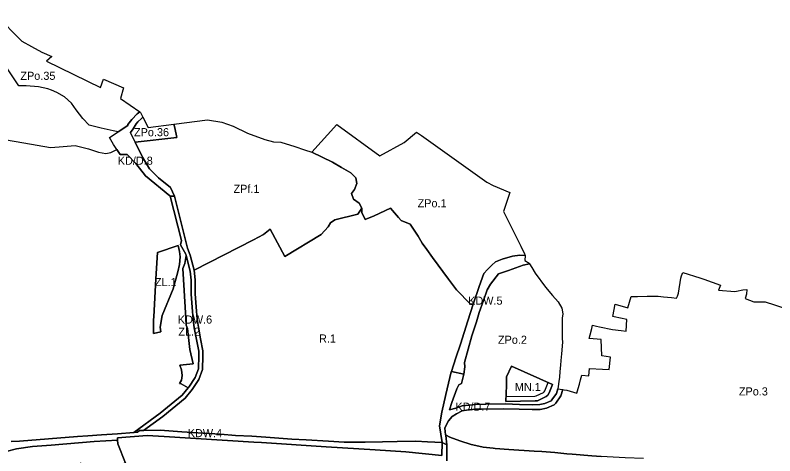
# Model space of a CAD drawing. Extents: x 7418114 to 7422197, y 5546299 to 5548348.
# Drawn here: x 7420780 to 7421715, y 5546924 to 5547467 of the extents above; entities that cross this region are included whole.
import ezdxf

# ---------------------------------------------------------------- set-up
doc = ezdxf.new("R2010")
doc.units = 0
for name, color, linetype in [('linie_rozgraniczajace', 7, 'Continuous'), ('linie_zabudowy_nieprzekraczalne', 7, 'Continuous'), ('oznaczenia_przeznaczen', 7, 'Continuous')]:
    doc.layers.add(name, color=color, linetype=linetype)

msp = doc.modelspace()

# ---------------------------------------------------------------- linework, layer by layer
at = {"layer": 'linie_rozgraniczajace'}
for p, q in [((7420848.94, 5547358.77), (7420840.46, 5547366.61)), ((7420906.75, 5547323.63), (7420900.3, 5547324.6)), ((7420853.71, 5547306.48), (7420863.38, 5547304.03)), ((7420863.38, 5547304.03), (7420870.04, 5547302.58)), ((7420870.04, 5547302.58), (7420882.2, 5547298.37)), ((7420897.71, 5547298.15), (7420905, 5547301.7)), ((7420905, 5547301.7), (7420900.69, 5547308.08)), ((7420882.2, 5547298.37), (7420886.67, 5547297.44)), ((7420886.67, 5547297.44), (7420891.21, 5547297)), ((7420891.21, 5547297), (7420897.71, 5547298.15))]:
    msp.add_line(p, q, dxfattribs=at)
for points in [[(7420755.7, 5547467.33), (7420788.05, 5547435.17), (7420799.97, 5547428.69), (7420812.48, 5547421.89), (7420824.78, 5547416.5), (7420818.18, 5547410.75), (7420884.81, 5547378.13), (7420888.64, 5547388.54), (7420912.93, 5547377.91), (7420909.33, 5547364.68), (7420933.14, 5547348.16), (7420930.01, 5547345.78), (7420923.47, 5547338.66), (7420918.57, 5547332.51), (7420918.34, 5547331.34), (7420906.75, 5547323.63), (7420900.3, 5547324.6), (7420885.46, 5547328.05), (7420870.84, 5547331.74), (7420863.11, 5547340.12), (7420854.99, 5547350.81), (7420848.94, 5547358.77), (7420840.46, 5547366.61), (7420830.83, 5547372.15), (7420824.32, 5547374.72), (7420820.08, 5547376.4), (7420808.49, 5547378.96), (7420793.14, 5547380.06), (7420784.27, 5547380.38), (7420769.29, 5547402.43)], [(7420784.27, 5547380.38), (7420769.29, 5547402.43), (7420760.2, 5547415.82), (7420752.51, 5547429.86)], [(7420820.08, 5547376.4), (7420808.49, 5547378.96), (7420793.14, 5547380.06), (7420784.27, 5547380.38)], [(7420840.46, 5547366.61), (7420830.83, 5547372.15), (7420824.32, 5547374.72), (7420820.08, 5547376.4)], [(7420870.84, 5547331.74), (7420863.11, 5547340.12), (7420854.99, 5547350.81), (7420848.94, 5547358.77)], [(7420900.3, 5547324.6), (7420885.46, 5547328.05), (7420870.84, 5547331.74)], [(7420900.69, 5547308.08), (7420895.74, 5547316.62), (7420906.75, 5547323.63)], [(7420746.49, 5547316.58), (7420754.04, 5547316.24), (7420790.41, 5547309.92)], [(7420754.04, 5547316.24), (7420790.41, 5547309.92), (7420823, 5547304.12), (7420833.98, 5547304.98), (7420843.84, 5547305.73), (7420853.71, 5547306.48), (7420863.38, 5547304.03), (7420870.04, 5547302.58), (7420882.2, 5547298.37), (7420886.67, 5547297.44), (7420891.21, 5547297), (7420897.71, 5547298.15), (7420905, 5547301.7), (7420909.2, 5547295.48), (7420917.46, 5547295.59), (7420928.43, 5547284.42), (7420940.09, 5547269.14), (7420970.4, 5547244.69), (7420970.79, 5547244.02), (7420984.37, 5547189.51), (7420983.19, 5547184.22), (7420989.89, 5547172.7), (7420990.3, 5547171.11), (7420988.51, 5547161.3), (7420986.38, 5547155.05), (7420989.85, 5547093.9), (7420990.41, 5547085.17), (7420991.81, 5547081.14), (7420994.94, 5547055.19), (7420998.85, 5547037.4), (7420982.49, 5547035.93), (7420984.73, 5547030), (7420985.35, 5547023.32), (7420984.42, 5547017.47), (7420982.27, 5547013.06), (7420984.04, 5547012.74), (7420992.93, 5547007.86), (7420985.42, 5546998.83), (7420958.36, 5546976.54), (7420925.88, 5546953), (7420905.56, 5546951.08), (7420885.83, 5546949.82), (7420869.07, 5546948.7), (7420856.43, 5546947.93), (7420785.11, 5546942.04), (7420774.73, 5546941.68)], [(7420790.41, 5547309.92), (7420823, 5547304.12), (7420833.98, 5547304.98)], [(7420833.98, 5547304.98), (7420843.84, 5547305.73), (7420853.71, 5547306.48)], [(7421309.16, 5546958.19), (7421310.78, 5546961.76), (7421313.49, 5546967.38), (7421318.15, 5546972.4), (7421323.46, 5546976.06), (7421330.49, 5546979.47), (7421335.66, 5546980.5), (7421346.91, 5546981.53), (7421353.96, 5546981.76), (7421380.66, 5546982.14), (7421400.54, 5546981.42), (7421416.37, 5546981.06), (7421426.44, 5546981.31), (7421434.07, 5546982.73), (7421443.45, 5546987.04), (7421445.54, 5546989.07), (7421451.94, 5546998.25), (7421454.17, 5547005.69), (7421455.93, 5547005.56), (7421459.23, 5547004.89), (7421467.51, 5547002.72), (7421471.51, 5547001.5), (7421473.08, 5547006.97), (7421474.66, 5547012.43), (7421476.23, 5547017.9), (7421477.79, 5547023.36), (7421486.25, 5547022.64), (7421487.04, 5547031.93), (7421503.14, 5547030.94), (7421511.34, 5547030.44), (7421513.09, 5547045.8), (7421502.5, 5547047.38), (7421501.54, 5547067.5), (7421486.77, 5547068.57), (7421488.15, 5547073.17), (7421490.15, 5547081.13), (7421490.87, 5547085.09), (7421495.92, 5547083.82), (7421499.57, 5547082.94), (7421515.54, 5547079.98), (7421526.02, 5547078.69), (7421532.45, 5547077.75), (7421533.16, 5547092.32), (7421517.74, 5547095.59), (7421515.82, 5547096.02), (7421518.73, 5547110.97), (7421534.58, 5547106.51), (7421538.37, 5547120.38), (7421546.1, 5547120.65), (7421558.32, 5547120.87), (7421568.43, 5547120.82), (7421571.57, 5547120.85), (7421578.42, 5547120.06), (7421588.37, 5547119.17), (7421594.51, 5547118.59), (7421595.53, 5547120.85), (7421596.67, 5547124.7), (7421599.81, 5547143.27), (7421600.46, 5547145.96), (7421602.31, 5547150.03), (7421622.9, 5547143.56), (7421628.1, 5547142.02), (7421648.52, 5547134.69), (7421645.93, 5547128.13), (7421666.06, 5547126.77), (7421668.06, 5547127.07), (7421676.05, 5547128.55), (7421681, 5547129.28), (7421680.5, 5547123.33), (7421678.8, 5547118.07), (7421689.77, 5547113.97), (7421703.49, 5547113.94), (7421715.19, 5547110.07), (7421735.26, 5547103.68)], [(7420774.73, 5546941.68), (7420785.11, 5546942.04), (7420856.43, 5546947.93), (7420869.07, 5546948.7), (7420885.83, 5546949.82), (7420905.56, 5546951.08), (7420925.88, 5546953), (7420930.46, 5546953.33), (7420932.76, 5546955.28), (7420937.58, 5546955.3), (7420958.41, 5546955.55), (7420985.17, 5546953.8), (7421011.27, 5546952.07), (7421032.65, 5546950.63), (7421051.26, 5546949.21), (7421071.05, 5546948.17), (7421088.46, 5546947.14), (7421120.6, 5546944.77), (7421138.24, 5546943.68), (7421165.85, 5546942.22), (7421184.97, 5546940.91), (7421186.8, 5546940.92), (7421191.02, 5546940.94), (7421210.63, 5546941), (7421232.13, 5546941.32), (7421250.43, 5546941.56), (7421273.04, 5546941.99), (7421287.41, 5546941.22), (7421305.82, 5546940.37), (7421305.36, 5546924.62), (7421260.81, 5546929.05), (7421223.26, 5546931.66), (7421162.97, 5546935.27), (7421083.04, 5546940.39), (7421073.86, 5546941.01), (7420963.39, 5546947.99), (7420942.2, 5546948.96), (7420905.57, 5546946.29), (7420905.73, 5546943.27), (7420877.16, 5546941.96), (7420824.16, 5546937.23), (7420800.87, 5546935.66), (7420781.14, 5546932.55), (7420755.47, 5546926.13)], [(7421553.79, 5546920.97), (7421531.13, 5546921.5), (7421501.59, 5546923.39), (7421490.21, 5546924.11), (7421465.88, 5546926.04), (7421459.32, 5546926.73), (7421444.63, 5546928.26), (7421428.25, 5546929.53), (7421419.1, 5546930.04), (7421387.96, 5546931.78), (7421371, 5546933.14), (7421368.66, 5546933.37), (7421356.1, 5546934.62), (7421343.52, 5546937.64), (7421341.49, 5546938.24), (7421327.31, 5546942.41), (7421315.01, 5546947.03), (7421309.95, 5546950.02), (7421309.16, 5546958.19)], [(7420915.67, 5546915.2), (7420906, 5546938.81), (7420905.73, 5546943.27), (7420905.57, 5546946.29), (7420942.2, 5546948.96), (7420963.39, 5546947.99), (7421073.86, 5546941.01), (7421083.04, 5546940.39), (7421162.97, 5546935.27), (7421223.26, 5546931.66), (7421260.81, 5546929.05), (7421305.36, 5546924.62), (7421305.82, 5546940.37), (7421311.45, 5546937.53), (7421311.28, 5546917.83)], [(7421311.28, 5546917.83), (7421311.45, 5546937.53), (7421310.04, 5546949.15), (7421309.95, 5546950.02), (7421315.01, 5546947.03), (7421327.31, 5546942.41), (7421341.49, 5546938.24), (7421343.52, 5546937.64), (7421356.1, 5546934.62), (7421368.66, 5546933.37), (7421371, 5546933.14), (7421387.96, 5546931.78), (7421419.1, 5546930.04), (7421428.25, 5546929.53), (7421444.63, 5546928.26), (7421459.32, 5546926.73), (7421465.88, 5546926.04), (7421490.21, 5546924.11), (7421501.59, 5546923.39)], [(7420755.47, 5546926.13), (7420781.14, 5546932.55), (7420800.87, 5546935.66), (7420824.16, 5546937.23), (7420877.16, 5546941.96), (7420905.73, 5546943.27), (7420906, 5546938.81), (7420915.67, 5546915.2), (7420898.14, 5546911.45), (7420877.93, 5546907.06), (7420857.9, 5546902.82), (7420855.94, 5546907.32), (7420862.19, 5546911.74), (7420860.39, 5546914.87), (7420854.39, 5546910.97), (7420851.46, 5546907.91), (7420850.11, 5546903.94), (7420846.65, 5546902.19), (7420776.89, 5546885.89)]]:
    msp.add_lwpolyline(points, dxfattribs=at)
for points in [[(7420895.74, 5547316.62), (7420906.75, 5547323.63), (7420918.34, 5547331.34), (7420918.57, 5547332.51), (7420923.47, 5547338.66), (7420930.01, 5547345.78), (7420933.14, 5547348.16), (7420934.09, 5547347.5), (7420937.12, 5547341.45), (7420935.19, 5547339.92), (7420930.58, 5547335.73), (7420928.54, 5547333.28), (7420924.86, 5547327.08), (7420921.71, 5547322.71), (7420921.93, 5547322.13), (7420927.53, 5547310.69), (7420936.59, 5547292.18), (7420945.09, 5547277.81), (7420956.17, 5547266.81), (7420971.18, 5547254.74), (7420975.94, 5547244.06), (7420970.79, 5547244.02), (7420970.4, 5547244.69), (7420940.09, 5547269.14), (7420928.43, 5547284.42), (7420917.46, 5547295.59), (7420909.2, 5547295.48), (7420905, 5547301.7), (7420900.69, 5547308.08)], [(7420921.71, 5547322.71), (7420924.86, 5547327.08), (7420928.54, 5547333.28), (7420930.58, 5547335.73), (7420935.19, 5547339.92), (7420937.12, 5547341.45), (7420943.45, 5547328.81), (7420975.11, 5547332.85), (7420976.39, 5547328.59), (7420978.95, 5547316.33), (7420927.53, 5547310.69), (7420921.93, 5547322.13)], [(7420927.53, 5547310.69), (7420978.95, 5547316.33), (7420976.39, 5547328.59), (7420975.11, 5547332.85), (7421016.64, 5547338.14), (7421034.16, 5547335.53), (7421048.25, 5547330.61), (7421066.03, 5547321.79), (7421087.3, 5547313.88), (7421097.82, 5547311.2), (7421106.92, 5547310.78), (7421124.07, 5547305.62), (7421136.27, 5547301.4), (7421145.17, 5547298.52), (7421170.73, 5547286.03), (7421181.86, 5547279.59), (7421193.04, 5547273.11), (7421199.32, 5547266.67), (7421200.59, 5547260), (7421197.82, 5547252.28), (7421194.01, 5547247.33), (7421196.26, 5547240.51), (7421203.25, 5547235.39), (7421206.9, 5547229.23), (7421201.95, 5547222.16), (7421173.5, 5547215.05), (7421168.02, 5547211.45), (7421165.44, 5547206.45), (7421156.58, 5547196.86), (7421111.67, 5547169.9), (7421093.94, 5547203.43), (7421085.6, 5547196.9), (7421073.08, 5547190.27), (7421000.22, 5547152.81), (7420995.37, 5547171.51), (7420991.82, 5547180.19), (7420982.91, 5547216.19), (7420975.94, 5547244.06), (7420971.18, 5547254.74), (7420956.17, 5547266.81), (7420945.09, 5547277.81), (7420936.59, 5547292.18)], [(7421145.17, 5547298.52), (7421175.73, 5547332.73), (7421228.75, 5547293.92), (7421259.05, 5547310.22), (7421274.19, 5547323.24), (7421280.27, 5547318.89), (7421360.52, 5547261.53), (7421368.48, 5547257.24), (7421389.13, 5547248.59), (7421381.16, 5547225.43), (7421390.52, 5547206.46), (7421402.43, 5547182.71), (7421407.19, 5547173.27), (7421408.08, 5547171.27), (7421408.08, 5547171.26), (7421401.35, 5547171.32), (7421392.35, 5547170.3), (7421379.66, 5547166.52), (7421371.42, 5547163.06), (7421366.78, 5547159.31), (7421361.41, 5547153.8), (7421357.04, 5547148.83), (7421351.37, 5547132.76), (7421343.96, 5547111.22), (7421340.59, 5547110.91), (7421323.53, 5547128.62), (7421313.66, 5547141.86), (7421293.72, 5547168.53), (7421286.89, 5547178.31), (7421281.21, 5547186.14), (7421275.98, 5547195.03), (7421266.08, 5547209.74), (7421255.21, 5547214.26), (7421251.89, 5547217.96), (7421241.99, 5547229.47), (7421222.07, 5547219.96), (7421210.95, 5547215.31), (7421206.9, 5547223.98), (7421206.9, 5547229.23), (7421203.25, 5547235.39), (7421196.26, 5547240.51), (7421194.01, 5547247.33), (7421197.82, 5547252.28), (7421200.59, 5547260), (7421199.32, 5547266.67), (7421193.04, 5547273.11), (7421181.86, 5547279.59), (7421170.73, 5547286.03)], [(7420925.88, 5546953), (7420958.36, 5546976.54), (7420985.42, 5546998.83), (7420992.93, 5547007.86), (7420993.79, 5547008.9), (7421001.28, 5547020.66), (7421005.5, 5547031.37), (7421005.94, 5547047.62), (7421005.9, 5547053.08), (7421000.38, 5547081.96), (7420998.99, 5547092.11), (7420997.96, 5547101.99), (7420996.59, 5547123.46), (7420996.54, 5547140.64), (7420995.29, 5547151.9), (7420990.3, 5547171.11), (7420989.89, 5547172.7), (7420983.19, 5547184.22), (7420984.37, 5547189.51), (7420970.79, 5547244.02), (7420975.94, 5547244.06), (7420982.91, 5547216.19), (7420991.82, 5547180.19), (7420995.37, 5547171.51), (7421000.22, 5547152.81), (7421001.54, 5547140.93), (7421001.59, 5547123.63), (7421002.94, 5547102.4), (7421003.96, 5547092.71), (7421005.31, 5547082.77), (7421008.11, 5547068.17), (7421010.9, 5547053.57), (7421010.94, 5547047.57), (7421010.47, 5547030.35), (7421005.76, 5547018.38), (7420997.84, 5547005.94), (7420988.96, 5546995.27), (7420961.42, 5546972.58), (7420937.58, 5546955.3), (7420932.76, 5546955.28), (7420930.46, 5546953.33)], [(7420937.58, 5546955.3), (7420961.42, 5546972.58), (7420988.96, 5546995.27), (7420997.84, 5547005.94), (7421005.76, 5547018.38), (7421010.47, 5547030.35), (7421010.94, 5547047.57), (7421010.9, 5547053.57), (7421008.11, 5547068.17), (7421005.31, 5547082.77), (7421003.96, 5547092.71), (7421002.94, 5547102.4), (7421001.59, 5547123.63), (7421001.54, 5547140.93), (7421000.22, 5547152.81), (7421073.08, 5547190.27), (7421085.6, 5547196.9), (7421093.94, 5547203.43), (7421111.67, 5547169.9), (7421156.58, 5547196.86), (7421165.44, 5547206.45), (7421168.02, 5547211.45), (7421173.5, 5547215.05), (7421201.95, 5547222.16), (7421206.9, 5547229.23), (7421206.9, 5547223.98), (7421210.95, 5547215.31), (7421222.07, 5547219.96), (7421241.99, 5547229.47), (7421251.89, 5547217.96), (7421255.21, 5547214.26), (7421266.08, 5547209.74), (7421275.98, 5547195.03), (7421281.21, 5547186.14), (7421286.89, 5547178.31), (7421293.72, 5547168.53), (7421313.66, 5547141.86), (7421323.53, 5547128.62), (7421340.59, 5547110.91), (7421343.96, 5547111.22), (7421337.4, 5547090.52), (7421328.32, 5547061.79), (7421322.65, 5547044.89), (7421317.07, 5547028.16), (7421316.95, 5547027.81), (7421310.21, 5546999.79), (7421305.42, 5546977.95), (7421302.24, 5546961.27), (7421305.82, 5546940.37), (7421287.41, 5546941.22), (7421273.04, 5546941.99), (7421250.43, 5546941.56), (7421232.13, 5546941.32), (7421210.63, 5546941), (7421191.02, 5546940.94), (7421186.8, 5546940.92), (7421184.97, 5546940.91), (7421165.85, 5546942.22), (7421138.24, 5546943.68), (7421120.6, 5546944.77), (7421088.46, 5546947.14), (7421071.05, 5546948.17), (7421051.26, 5546949.21), (7421032.65, 5546950.63), (7421011.27, 5546952.07), (7420985.17, 5546953.8), (7420958.41, 5546955.55)], [(7420950.2, 5547074.74), (7420959.3, 5547076.87), (7420958.16, 5547082.76), (7420960.88, 5547097.02), (7420974.48, 5547130.08), (7420980.2, 5547150.75), (7420981.99, 5547159.87), (7420982.86, 5547169.31), (7420982.14, 5547176.01), (7420980.51, 5547183.35), (7420955.19, 5547174.88), (7420953.11, 5547142.43), (7420950.67, 5547095.3), (7420949.94, 5547091.63)], [(7420950.2, 5547074.74), (7420949.94, 5547091.63), (7420950.67, 5547095.3), (7420953.11, 5547142.43), (7420955.19, 5547174.88), (7420980.51, 5547183.35), (7420982.14, 5547176.01), (7420982.86, 5547169.31), (7420981.99, 5547159.87), (7420980.2, 5547150.75), (7420974.48, 5547130.08), (7420960.88, 5547097.02), (7420958.16, 5547082.76), (7420959.3, 5547076.87)], [(7420982.27, 5547013.06), (7420984.42, 5547017.47), (7420985.35, 5547023.32), (7420984.73, 5547030), (7420982.49, 5547035.93), (7420998.85, 5547037.4), (7420994.94, 5547055.19), (7420991.81, 5547081.14), (7420990.41, 5547085.17), (7420989.85, 5547093.9), (7420986.38, 5547155.05), (7420988.51, 5547161.3), (7420990.3, 5547171.11), (7420995.29, 5547151.9), (7420996.54, 5547140.64), (7420996.59, 5547123.46), (7420997.96, 5547101.99), (7420998.99, 5547092.11), (7421000.38, 5547081.96), (7421005.9, 5547053.08), (7421005.94, 5547047.62), (7421005.5, 5547031.37), (7421001.28, 5547020.66), (7420993.79, 5547008.9), (7420992.93, 5547007.86), (7420984.04, 5547012.74)], [(7421317.07, 5547028.16), (7421322.65, 5547044.89), (7421328.32, 5547061.79), (7421337.4, 5547090.52), (7421343.96, 5547111.22), (7421351.37, 5547132.76), (7421357.04, 5547148.83), (7421361.41, 5547153.8), (7421366.78, 5547159.31), (7421371.42, 5547163.06), (7421379.66, 5547166.52), (7421392.35, 5547170.3), (7421401.35, 5547171.32), (7421408.08, 5547171.26), (7421407.31, 5547164.97), (7421412.78, 5547161.67), (7421413.29, 5547160.82), (7421405.52, 5547159.21), (7421387.57, 5547152.71), (7421375.21, 5547148.39), (7421365.32, 5547135.74), (7421361.09, 5547128.85), (7421356.65, 5547115.4), (7421351.36, 5547100.66), (7421347.87, 5547089.09), (7421342.41, 5547071.94), (7421333.36, 5547039.09), (7421333.68, 5547033.73), (7421332.22, 5547024.79)], [(7421314.91, 5546980.62), (7421317.74, 5546989.68), (7421323.94, 5547006.89), (7421326.15, 5547011.5), (7421329.38, 5547013.18), (7421332.22, 5547024.79), (7421333.68, 5547033.73), (7421333.36, 5547039.09), (7421342.41, 5547071.94), (7421347.87, 5547089.09), (7421351.36, 5547100.66), (7421356.65, 5547115.4), (7421361.09, 5547128.85), (7421365.32, 5547135.74), (7421375.21, 5547148.39), (7421387.57, 5547152.71), (7421405.52, 5547159.21), (7421413.29, 5547160.82), (7421416.13, 5547156.1), (7421420.2, 5547149.41), (7421432.96, 5547131.9), (7421441.51, 5547121.68), (7421448.57, 5547113.86), (7421453.2, 5547106.22), (7421454.15, 5547098.98), (7421453.7, 5547094.01), (7421453.51, 5547080.47), (7421453.64, 5547068.8), (7421453.82, 5547064.31), (7421452.62, 5547049.85), (7421452.05, 5547041.76), (7421451.5, 5547035.86), (7421450.82, 5547028.18), (7421450.13, 5547020.97), (7421449.44, 5547015.71), (7421448.58, 5547009.56), (7421448.06, 5547006.73), (7421446.47, 5547000.89), (7421440.95, 5546992.97), (7421440.01, 5546992.06), (7421432.25, 5546988.49), (7421425.81, 5546987.3), (7421416.36, 5546987.06), (7421400.74, 5546987.42), (7421383.69, 5546988.17), (7421359.58, 5546987.94), (7421346.72, 5546987.53), (7421330.43, 5546985.89), (7421322.62, 5546982.79)], [(7421384.14, 5546991.18), (7421420.09, 5546991.83), (7421423.01, 5546992.04), (7421433.8, 5546997.23), (7421435.82, 5546999.03), (7421437.43, 5547001.62), (7421441.65, 5547011.97), (7421391.18, 5547034.46), (7421384.75, 5547021.52), (7421385.1, 5547010.75)], [(7421384.14, 5546991.18), (7421385.1, 5547010.75), (7421384.75, 5547021.52), (7421391.18, 5547034.46), (7421441.65, 5547011.97), (7421437.43, 5547001.62), (7421435.82, 5546999.03), (7421433.8, 5546997.23), (7421423.01, 5546992.04), (7421420.09, 5546991.83)], [(7421302.24, 5546961.27), (7421305.42, 5546977.95), (7421310.21, 5546999.79), (7421316.95, 5547027.81), (7421317.07, 5547028.16), (7421332.22, 5547024.79), (7421329.38, 5547013.18), (7421326.15, 5547011.5), (7421323.94, 5547006.89), (7421317.74, 5546989.68), (7421314.91, 5546980.62), (7421322.62, 5546982.79), (7421330.43, 5546985.89), (7421346.72, 5546987.53), (7421359.58, 5546987.94), (7421383.69, 5546988.17), (7421400.74, 5546987.42), (7421416.36, 5546987.06), (7421425.81, 5546987.3), (7421432.25, 5546988.49), (7421440.01, 5546992.06), (7421440.95, 5546992.97), (7421446.47, 5547000.89), (7421448.06, 5547006.73), (7421453.93, 5547005.71), (7421454.17, 5547005.69), (7421451.94, 5546998.25), (7421445.54, 5546989.07), (7421443.45, 5546987.04), (7421434.07, 5546982.73), (7421426.44, 5546981.31), (7421416.37, 5546981.06), (7421400.54, 5546981.42), (7421380.66, 5546982.14), (7421353.96, 5546981.76), (7421346.91, 5546981.53), (7421335.66, 5546980.5), (7421330.49, 5546979.47), (7421323.46, 5546976.06), (7421318.15, 5546972.4), (7421313.49, 5546967.38), (7421310.78, 5546961.76), (7421309.16, 5546958.19), (7421309.95, 5546950.02), (7421310.04, 5546949.15), (7421311.45, 5546937.53), (7421305.82, 5546940.37)]]:
    msp.add_lwpolyline(points, close=True, dxfattribs=at)
at = {"layer": 'linie_zabudowy_nieprzekraczalne'}
msp.add_lwpolyline([(7421384.43, 5546997.18), (7421419.81, 5546997.82), (7421421.44, 5546997.94), (7421430.44, 5547002.27), (7421431.18, 5547002.93), (7421432.06, 5547004.35), (7421436.17, 5547014.4)], dxfattribs=at)

# ---------------------------------------------------------------- texts
at = {"layer": 'oznaczenia_przeznaczen'}
for s, p in [('ZPo.35', (7420786.11, 5547387.62)), ('ZPo.36', (7420926.08, 5547318.08)), ('KD/D.8', (7420906.07, 5547282.94)), ('ZPf.1', (7421048.62, 5547248.3)), ('ZPo.1', (7421275.38, 5547230.48)), ('ZL.1', (7420951.78, 5547133.31)), ('KDW.5', (7421337.67, 5547110.4)), ('KDW.6', (7420980.01, 5547087.11)), ('ZL.2', (7420980.68, 5547072.17)), ('R.1', (7421154.04, 5547063.69)), ('ZPo.2', (7421374.4, 5547062.18)), ('MN.1', (7421395.21, 5547004.08)), ('ZPo.3', (7421671.19, 5546998.54)), ('KD/D.7', (7421321.96, 5546979.72)), ('KDW.4', (7420992.29, 5546947.07))]:
    msp.add_text(s, height=10, dxfattribs=at).set_placement(p)

doc.saveas('drawing.dxf')
